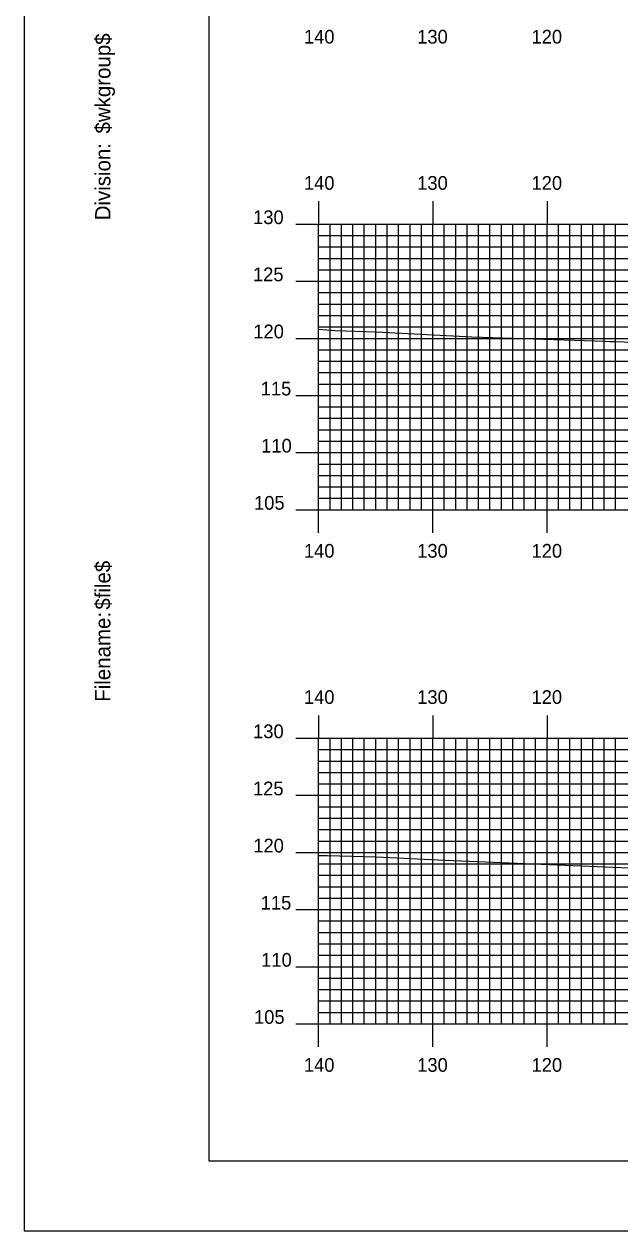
# Model space of a CAD drawing. Extents: x 1771629 to 1771972, y 442591 to 442811.
# Drawn here: x 1771628.8 to 1771681, y 442590.5 to 442696.2 of the extents above; entities that cross this region are included whole.
import ezdxf

# ---------------------------------------------------------------- set-up
doc = ezdxf.new("R2010")
doc.units = 0
for name, color, linetype in [('BORDER', 7, 'Continuous'), ('H_V ANNOTATION', 7, 'Continuous'), ('MAJOR', 7, 'Continuous'), ('MINOR', 7, 'Continuous'), ('PLOT BOUNDARY', 7, 'Continuous'), ('S_Roadway_Centerline', 7, 'Continuous')]:
    doc.layers.add(name, color=color, linetype=linetype)

msp = doc.modelspace()

# ---------------------------------------------------------------- linework, layer by layer
at = {"layer": 'BORDER'}
msp.add_lwpolyline([(1771644.98, 442596.67), (1771964.98, 442596.67), (1771964.98, 442806.67), (1771644.98, 442806.67)], close=True, dxfattribs=at)
at = {"layer": 'MAJOR'}
for p, q in [((1771654.58, 442680.67), (1771654.58, 442678.67)), ((1771664.58, 442680.67), (1771664.58, 442678.67)), ((1771674.58, 442680.67), (1771674.58, 442678.67)), ((1771652.58, 442678.67), (1771654.58, 442678.67)), ((1771654.58, 442678.67), (1771934.58, 442678.67)), ((1771654.58, 442653.67), (1771654.58, 442678.67)), ((1771654.58, 442653.67), (1771654.58, 442678.67)), ((1771654.58, 442678.67), (1771934.58, 442678.67)), ((1771664.58, 442653.67), (1771664.58, 442678.67)), ((1771674.58, 442653.67), (1771674.58, 442678.67)), ((1771652.58, 442673.67), (1771654.58, 442673.67)), ((1771654.58, 442673.67), (1771934.58, 442673.67)), ((1771652.58, 442668.67), (1771654.58, 442668.67)), ((1771654.58, 442668.67), (1771934.58, 442668.67)), ((1771652.58, 442663.67), (1771654.58, 442663.67)), ((1771654.58, 442663.67), (1771934.58, 442663.67)), ((1771652.58, 442658.67), (1771654.58, 442658.67)), ((1771654.58, 442658.67), (1771934.58, 442658.67)), ((1771652.58, 442653.67), (1771654.58, 442653.67)), ((1771654.58, 442653.67), (1771934.58, 442653.67)), ((1771654.58, 442653.67), (1771934.58, 442653.67)), ((1771654.58, 442651.66), (1771654.58, 442653.67)), ((1771664.58, 442651.66), (1771664.58, 442653.67)), ((1771674.58, 442651.66), (1771674.58, 442653.67)), ((1771654.58, 442635.67), (1771654.58, 442633.67)), ((1771664.58, 442635.67), (1771664.58, 442633.67)), ((1771674.58, 442635.67), (1771674.58, 442633.67)), ((1771652.58, 442633.67), (1771654.58, 442633.67)), ((1771654.58, 442633.67), (1771934.58, 442633.67)), ((1771654.58, 442608.67), (1771654.58, 442633.67)), ((1771654.58, 442608.67), (1771654.58, 442633.67)), ((1771654.58, 442633.67), (1771934.58, 442633.67)), ((1771664.58, 442608.67), (1771664.58, 442633.67)), ((1771674.58, 442608.67), (1771674.58, 442633.67)), ((1771652.58, 442628.67), (1771654.58, 442628.67)), ((1771654.58, 442628.67), (1771934.58, 442628.67)), ((1771652.58, 442623.67), (1771654.58, 442623.67)), ((1771654.58, 442623.67), (1771934.58, 442623.67)), ((1771652.58, 442618.67), (1771654.58, 442618.67)), ((1771654.58, 442618.67), (1771934.58, 442618.67)), ((1771652.58, 442613.67), (1771654.58, 442613.67)), ((1771654.58, 442613.67), (1771934.58, 442613.67)), ((1771652.58, 442608.67), (1771654.58, 442608.67)), ((1771654.58, 442608.67), (1771934.58, 442608.67)), ((1771654.58, 442608.67), (1771934.58, 442608.67)), ((1771654.58, 442606.66), (1771654.58, 442608.67)), ((1771664.58, 442606.66), (1771664.58, 442608.67)), ((1771674.58, 442606.66), (1771674.58, 442608.67))]:
    msp.add_line(p, q, dxfattribs=at)
at = {"layer": 'MINOR'}
for p, q in [((1771655.58, 442653.67), (1771655.58, 442678.67)), ((1771656.58, 442653.67), (1771656.58, 442678.67)), ((1771657.58, 442653.67), (1771657.58, 442678.67)), ((1771658.58, 442653.67), (1771658.58, 442678.67)), ((1771659.58, 442653.67), (1771659.58, 442678.67)), ((1771660.58, 442653.67), (1771660.58, 442678.67)), ((1771661.58, 442653.67), (1771661.58, 442678.67)), ((1771662.58, 442653.67), (1771662.58, 442678.67)), ((1771663.58, 442653.67), (1771663.58, 442678.67)), ((1771665.58, 442653.67), (1771665.58, 442678.67)), ((1771666.58, 442653.67), (1771666.58, 442678.67)), ((1771667.58, 442653.67), (1771667.58, 442678.67)), ((1771668.58, 442653.67), (1771668.58, 442678.67)), ((1771669.58, 442653.67), (1771669.58, 442678.67)), ((1771670.58, 442653.67), (1771670.58, 442678.67)), ((1771671.58, 442653.67), (1771671.58, 442678.67)), ((1771672.58, 442653.67), (1771672.58, 442678.67)), ((1771673.58, 442653.67), (1771673.58, 442678.67)), ((1771675.58, 442653.67), (1771675.58, 442678.67)), ((1771676.58, 442653.67), (1771676.58, 442678.67)), ((1771677.58, 442653.67), (1771677.58, 442678.67)), ((1771678.58, 442653.67), (1771678.58, 442678.67)), ((1771679.58, 442653.67), (1771679.58, 442678.67)), ((1771680.58, 442653.67), (1771680.58, 442678.67)), ((1771654.58, 442677.67), (1771934.58, 442677.67)), ((1771654.58, 442677.67), (1771656.58, 442677.67)), ((1771654.58, 442676.67), (1771934.58, 442676.67)), ((1771654.58, 442676.67), (1771656.58, 442676.67)), ((1771654.58, 442675.67), (1771934.58, 442675.67)), ((1771654.58, 442675.67), (1771656.58, 442675.67)), ((1771654.58, 442674.67), (1771934.58, 442674.67)), ((1771654.58, 442674.67), (1771656.58, 442674.67)), ((1771654.58, 442672.67), (1771934.58, 442672.67)), ((1771654.58, 442672.67), (1771656.58, 442672.67)), ((1771654.58, 442671.67), (1771934.58, 442671.67)), ((1771654.58, 442671.67), (1771656.58, 442671.67)), ((1771654.58, 442670.67), (1771934.58, 442670.67)), ((1771654.58, 442670.67), (1771656.58, 442670.67)), ((1771654.58, 442669.67), (1771934.58, 442669.67)), ((1771654.58, 442669.67), (1771656.58, 442669.67)), ((1771654.58, 442667.67), (1771934.58, 442667.67)), ((1771654.58, 442667.67), (1771656.58, 442667.67)), ((1771654.58, 442666.67), (1771934.58, 442666.67)), ((1771654.58, 442666.67), (1771656.58, 442666.67)), ((1771654.58, 442665.67), (1771934.58, 442665.67)), ((1771654.58, 442665.67), (1771656.58, 442665.67)), ((1771654.58, 442664.67), (1771934.58, 442664.67)), ((1771654.58, 442664.67), (1771656.58, 442664.67)), ((1771654.58, 442662.67), (1771934.58, 442662.67)), ((1771654.58, 442662.67), (1771656.58, 442662.67)), ((1771654.58, 442661.67), (1771934.58, 442661.67)), ((1771654.58, 442661.67), (1771656.58, 442661.67)), ((1771654.58, 442660.67), (1771934.58, 442660.67)), ((1771654.58, 442660.67), (1771656.58, 442660.67)), ((1771654.58, 442659.67), (1771934.58, 442659.67)), ((1771654.58, 442659.67), (1771656.58, 442659.67)), ((1771654.58, 442657.67), (1771934.58, 442657.67)), ((1771654.58, 442657.67), (1771656.58, 442657.67)), ((1771654.58, 442656.67), (1771934.58, 442656.67)), ((1771654.58, 442656.67), (1771656.58, 442656.67)), ((1771654.58, 442655.67), (1771934.58, 442655.67)), ((1771654.58, 442655.67), (1771656.58, 442655.67)), ((1771654.58, 442654.67), (1771934.58, 442654.67)), ((1771654.58, 442654.67), (1771656.58, 442654.67)), ((1771655.58, 442608.67), (1771655.58, 442633.67)), ((1771656.58, 442608.67), (1771656.58, 442633.67)), ((1771657.58, 442608.67), (1771657.58, 442633.67)), ((1771658.58, 442608.67), (1771658.58, 442633.67)), ((1771659.58, 442608.67), (1771659.58, 442633.67)), ((1771660.58, 442608.67), (1771660.58, 442633.67)), ((1771661.58, 442608.67), (1771661.58, 442633.67)), ((1771662.58, 442608.67), (1771662.58, 442633.67)), ((1771663.58, 442608.67), (1771663.58, 442633.67)), ((1771665.58, 442608.67), (1771665.58, 442633.67)), ((1771666.58, 442608.67), (1771666.58, 442633.67)), ((1771667.58, 442608.67), (1771667.58, 442633.67)), ((1771668.58, 442608.67), (1771668.58, 442633.67)), ((1771669.58, 442608.67), (1771669.58, 442633.67)), ((1771670.58, 442608.67), (1771670.58, 442633.67)), ((1771671.58, 442608.67), (1771671.58, 442633.67)), ((1771672.58, 442608.67), (1771672.58, 442633.67)), ((1771673.58, 442608.67), (1771673.58, 442633.67)), ((1771675.58, 442608.67), (1771675.58, 442633.67)), ((1771676.58, 442608.67), (1771676.58, 442633.67)), ((1771677.58, 442608.67), (1771677.58, 442633.67)), ((1771678.58, 442608.67), (1771678.58, 442633.67)), ((1771679.58, 442608.67), (1771679.58, 442633.67)), ((1771680.58, 442608.67), (1771680.58, 442633.67)), ((1771654.58, 442632.67), (1771934.58, 442632.67)), ((1771654.58, 442632.67), (1771656.58, 442632.67)), ((1771654.58, 442631.67), (1771934.58, 442631.67)), ((1771654.58, 442631.67), (1771656.58, 442631.67)), ((1771654.58, 442630.67), (1771934.58, 442630.67)), ((1771654.58, 442630.67), (1771656.58, 442630.67)), ((1771654.58, 442629.67), (1771934.58, 442629.67)), ((1771654.58, 442629.67), (1771656.58, 442629.67)), ((1771654.58, 442627.67), (1771934.58, 442627.67)), ((1771654.58, 442627.67), (1771656.58, 442627.67)), ((1771654.58, 442626.67), (1771934.58, 442626.67)), ((1771654.58, 442626.67), (1771656.58, 442626.67)), ((1771654.58, 442625.67), (1771934.58, 442625.67)), ((1771654.58, 442625.67), (1771656.58, 442625.67)), ((1771654.58, 442624.67), (1771934.58, 442624.67)), ((1771654.58, 442624.67), (1771656.58, 442624.67)), ((1771654.58, 442622.67), (1771934.58, 442622.67)), ((1771654.58, 442622.67), (1771656.58, 442622.67)), ((1771654.58, 442621.67), (1771934.58, 442621.67)), ((1771654.58, 442621.67), (1771656.58, 442621.67)), ((1771654.58, 442620.67), (1771934.58, 442620.67)), ((1771654.58, 442620.67), (1771656.58, 442620.67)), ((1771654.58, 442619.67), (1771934.58, 442619.67)), ((1771654.58, 442619.67), (1771656.58, 442619.67)), ((1771654.58, 442617.67), (1771934.58, 442617.67)), ((1771654.58, 442617.67), (1771656.58, 442617.67)), ((1771654.58, 442616.67), (1771934.58, 442616.67)), ((1771654.58, 442616.67), (1771656.58, 442616.67)), ((1771654.58, 442615.67), (1771934.58, 442615.67)), ((1771654.58, 442615.67), (1771656.58, 442615.67)), ((1771654.58, 442614.67), (1771934.58, 442614.67)), ((1771654.58, 442614.67), (1771656.58, 442614.67)), ((1771654.58, 442612.67), (1771934.58, 442612.67)), ((1771654.58, 442612.67), (1771656.58, 442612.67)), ((1771654.58, 442611.67), (1771934.58, 442611.67)), ((1771654.58, 442611.67), (1771656.58, 442611.67)), ((1771654.58, 442610.67), (1771934.58, 442610.67)), ((1771654.58, 442610.67), (1771656.58, 442610.67)), ((1771654.58, 442609.67), (1771934.58, 442609.67)), ((1771654.58, 442609.67), (1771656.58, 442609.67))]:
    msp.add_line(p, q, dxfattribs=at)
at = {"layer": 'PLOT BOUNDARY'}
msp.add_lwpolyline([(1771628.79, 442590.55), (1771968.79, 442590.55), (1771968.79, 442810.55), (1771628.79, 442810.55)], close=True, dxfattribs=at)
at = {"layer": 'S_Roadway_Centerline'}
for points in [[(1771654.58, 442669.48), (1771656.04, 442669.36), (1771659.63, 442669.23), (1771668, 442668.8), (1771679.66, 442668.42), (1771680.08, 442668.4), (1771680.54, 442668.38), (1771699.38, 442667.69), (1771702.61, 442667.61), (1771707.23, 442667.46), (1771720.16, 442666.88), (1771735.05, 442666.53), (1771739.7, 442666.46), (1771749.35, 442666.64)], [(1771654.58, 442623.4), (1771655.33, 442623.39), (1771659.61, 442623.3), (1771665.66, 442622.98), (1771683.17, 442622.26), (1771692.87, 442621.95), (1771696.7, 442621.83), (1771706.7, 442621.49), (1771715.99, 442621.01), (1771722.32, 442620.81), (1771735.69, 442620.67), (1771741.62, 442620.72)]]:
    msp.add_lwpolyline(points, dxfattribs=at)

# ---------------------------------------------------------------- texts
at = {"layer": 'BORDER'}
for s, p in [('$wkgroup$', (1771636.35, 442686.6)), ('Division:', (1771636.35, 442679)), ('$file$', (1771636.35, 442644.92)), ('Filename:', (1771636.35, 442636.86))]:
    msp.add_text(s, height=1.339, rotation=90, dxfattribs=at).set_placement(p)
at = {"layer": 'H_V ANNOTATION'}
for s, p in [('140', (1771653.29, 442694.47)), ('130', (1771663.21, 442694.47)), ('120', (1771673.22, 442694.47)), ('140', (1771653.29, 442681.67)), ('130', (1771663.21, 442681.67)), ('120', (1771673.22, 442681.67)), ('130', (1771648.84, 442678.67)), ('125', (1771648.83, 442673.67)), ('120', (1771648.86, 442668.67)), ('115', (1771649.51, 442663.67)), ('110', (1771649.55, 442658.67)), ('105', (1771648.92, 442653.67)), ('140', (1771653.29, 442649.47)), ('130', (1771663.21, 442649.47)), ('120', (1771673.22, 442649.47)), ('140', (1771653.29, 442636.67)), ('130', (1771663.21, 442636.67)), ('120', (1771673.22, 442636.67)), ('130', (1771648.84, 442633.67)), ('125', (1771648.83, 442628.67)), ('120', (1771648.86, 442623.67)), ('115', (1771649.51, 442618.67)), ('110', (1771649.55, 442613.67)), ('105', (1771648.92, 442608.67)), ('140', (1771653.29, 442604.47)), ('130', (1771663.21, 442604.47)), ('120', (1771673.22, 442604.47))]:
    msp.add_text(s, height=1.2, dxfattribs=at).set_placement(p)
at = {"layer": 'MAJOR'}
for p in [(1771654.57, 442653.67), (1771654.57, 442608.67)]:
    msp.add_text('-', height=0.012, dxfattribs=at).set_placement(p)

doc.saveas('drawing.dxf')
